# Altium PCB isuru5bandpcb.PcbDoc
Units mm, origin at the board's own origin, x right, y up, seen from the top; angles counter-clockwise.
Board outline 152.4 x 101.6 mm, 4 copper layers (Top Layer, Layer 1, Layer 2, Bottom Layer), stack 2.6 mm thick; 87 components, 68 nets, 261 pads, 4 vias.
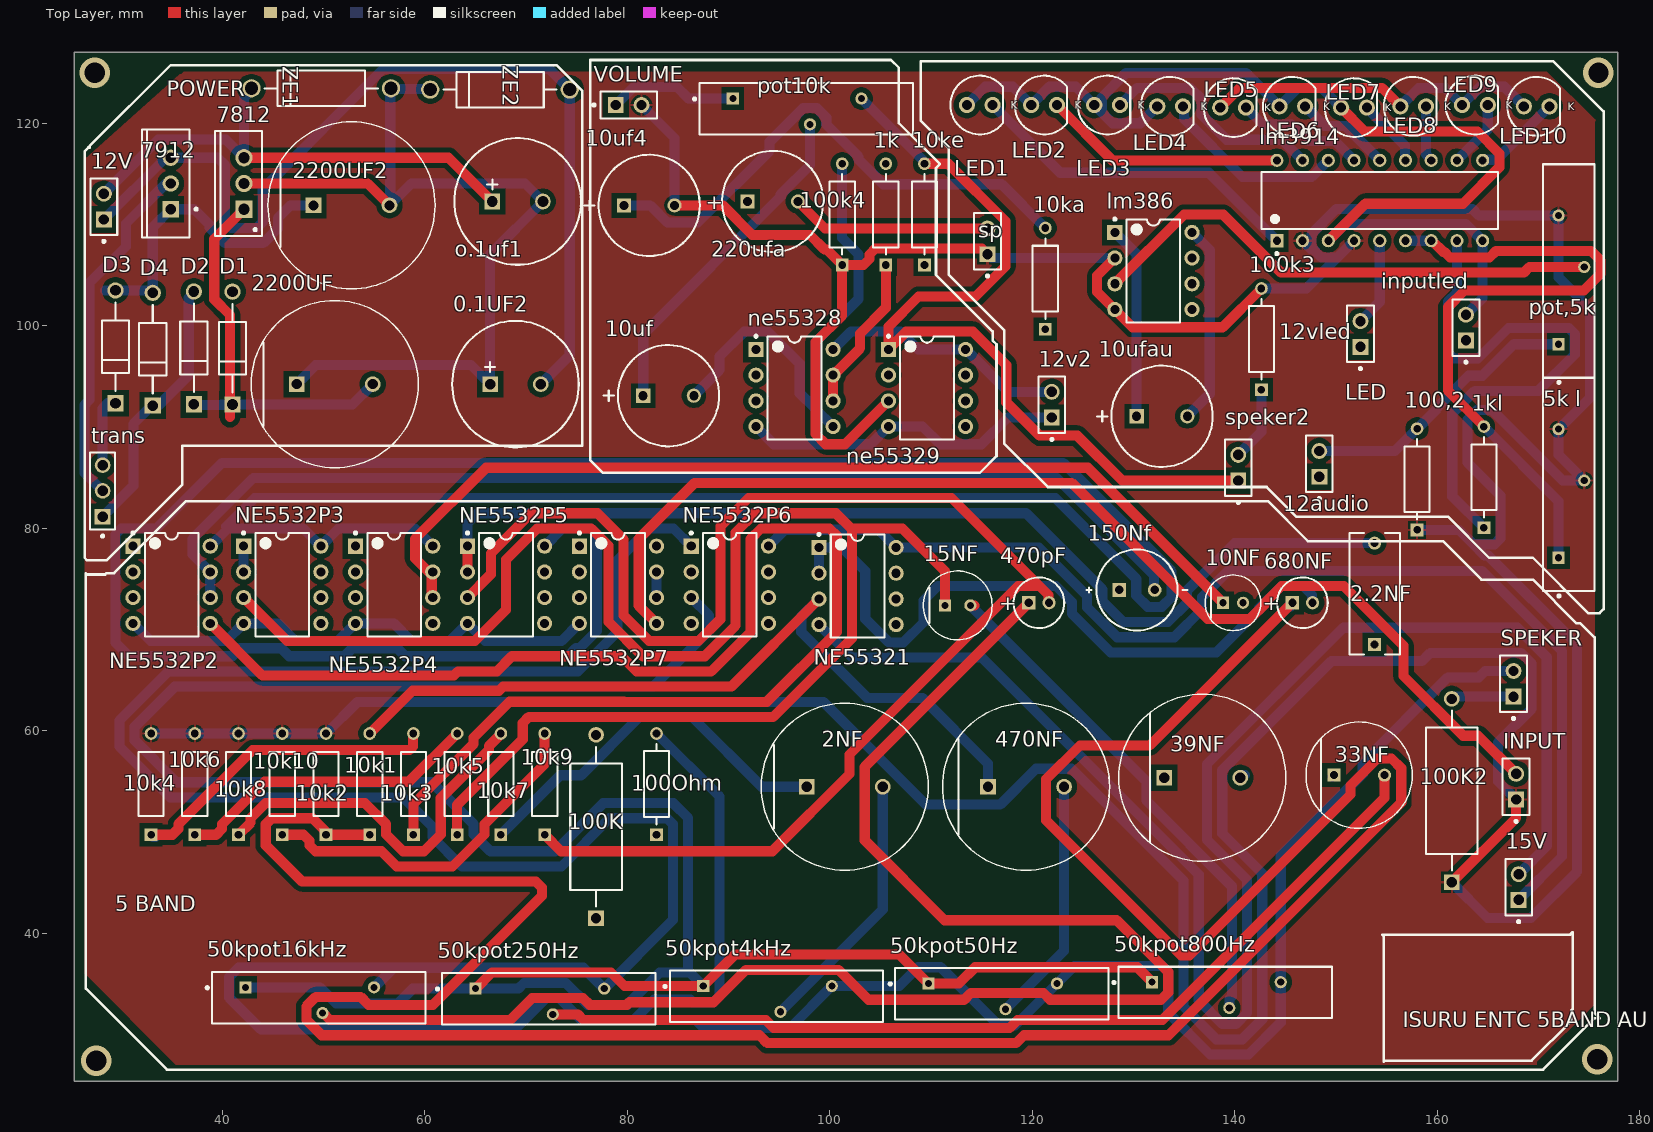
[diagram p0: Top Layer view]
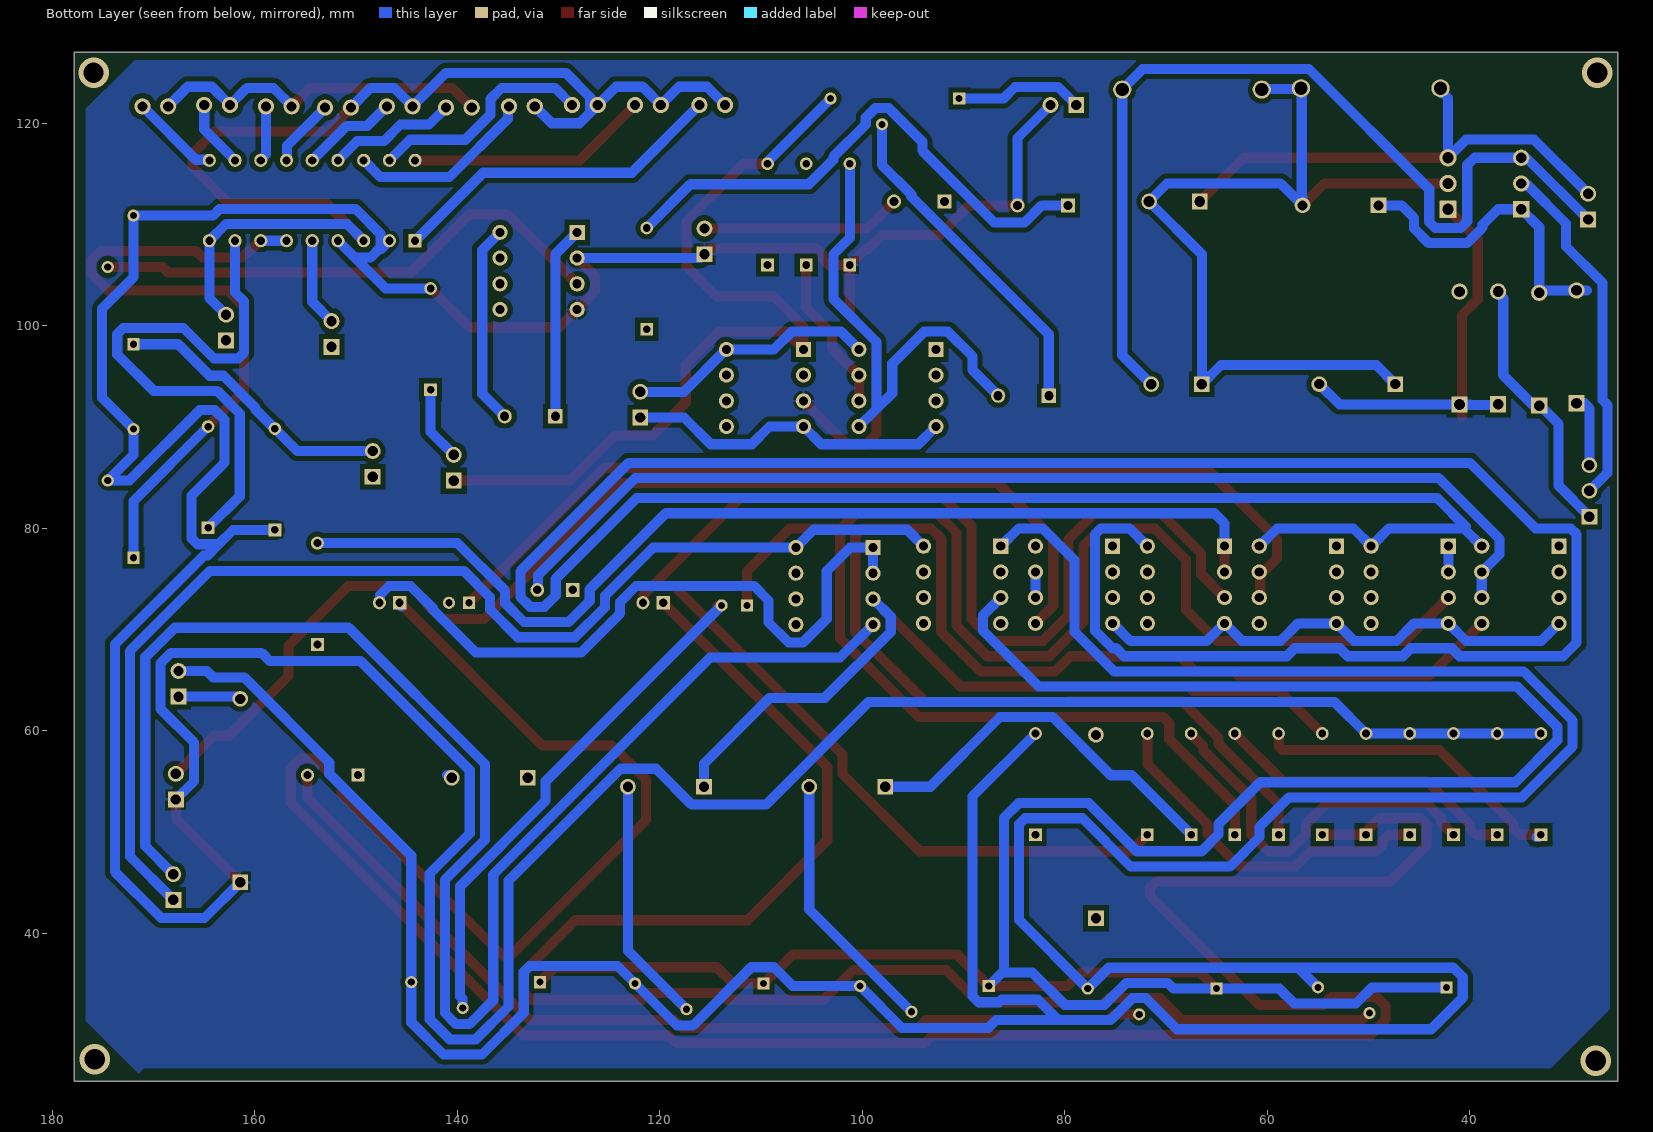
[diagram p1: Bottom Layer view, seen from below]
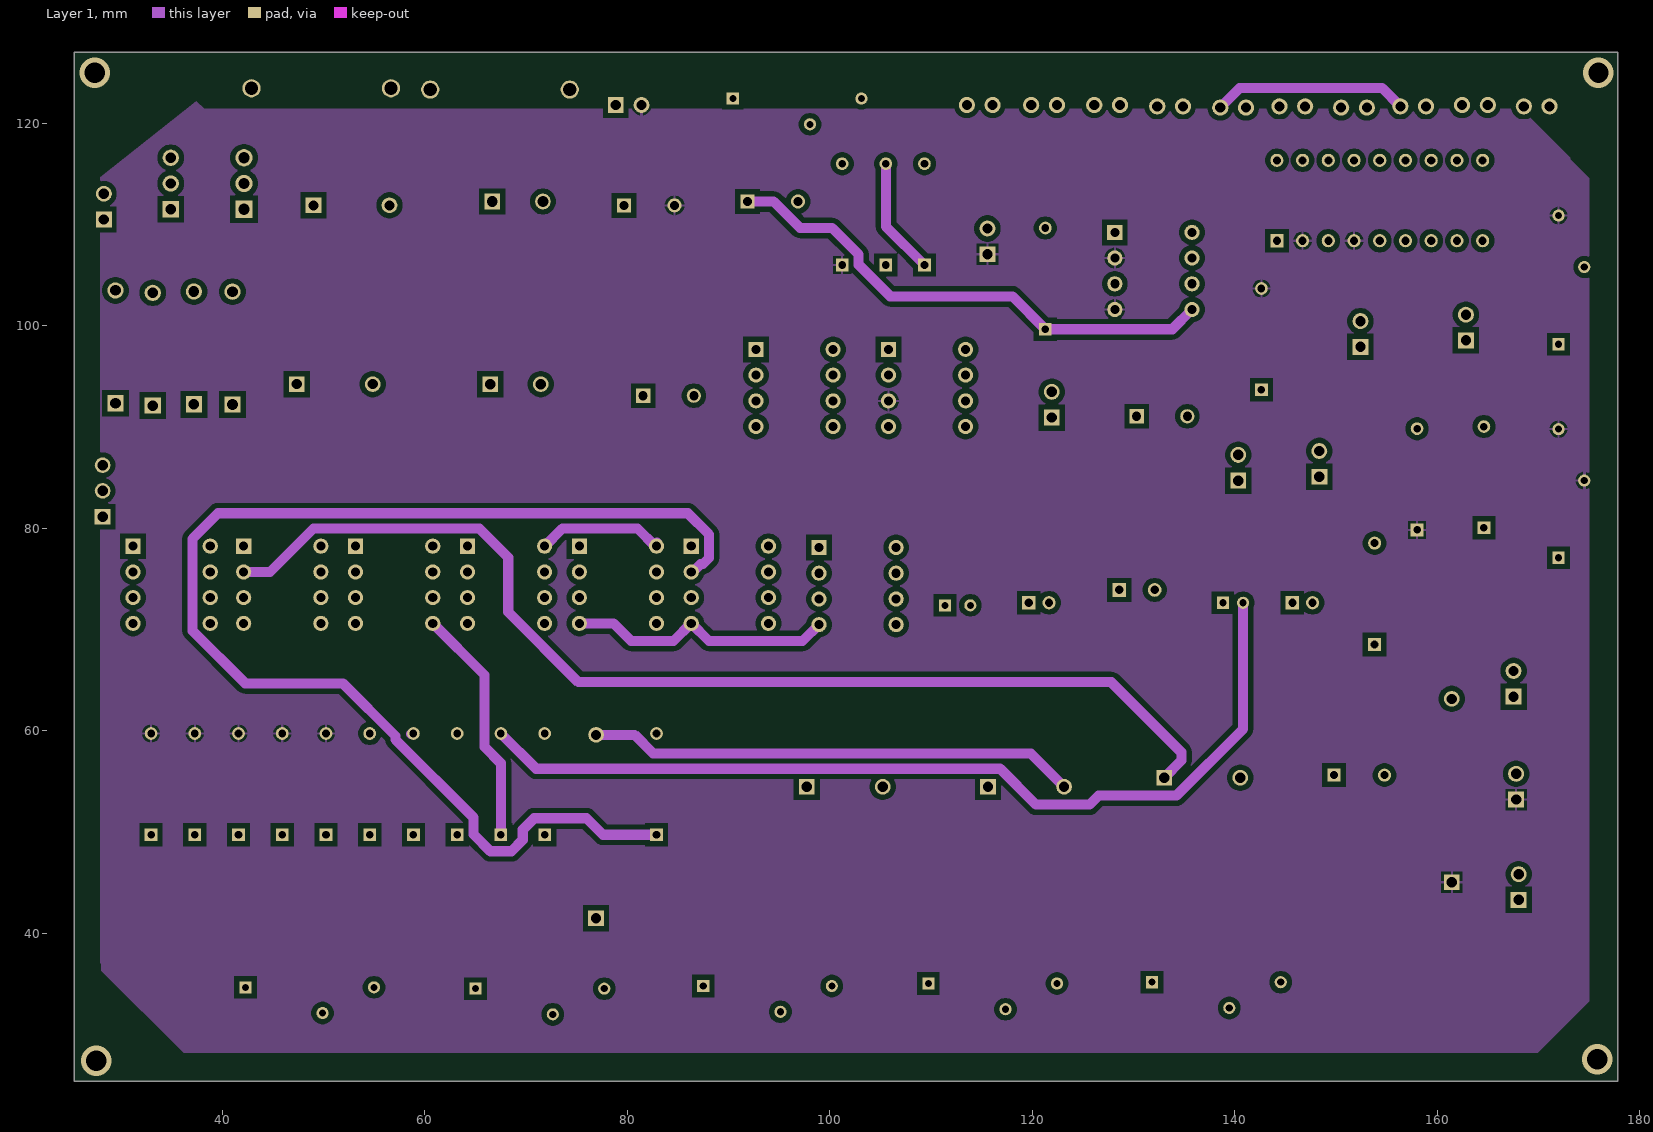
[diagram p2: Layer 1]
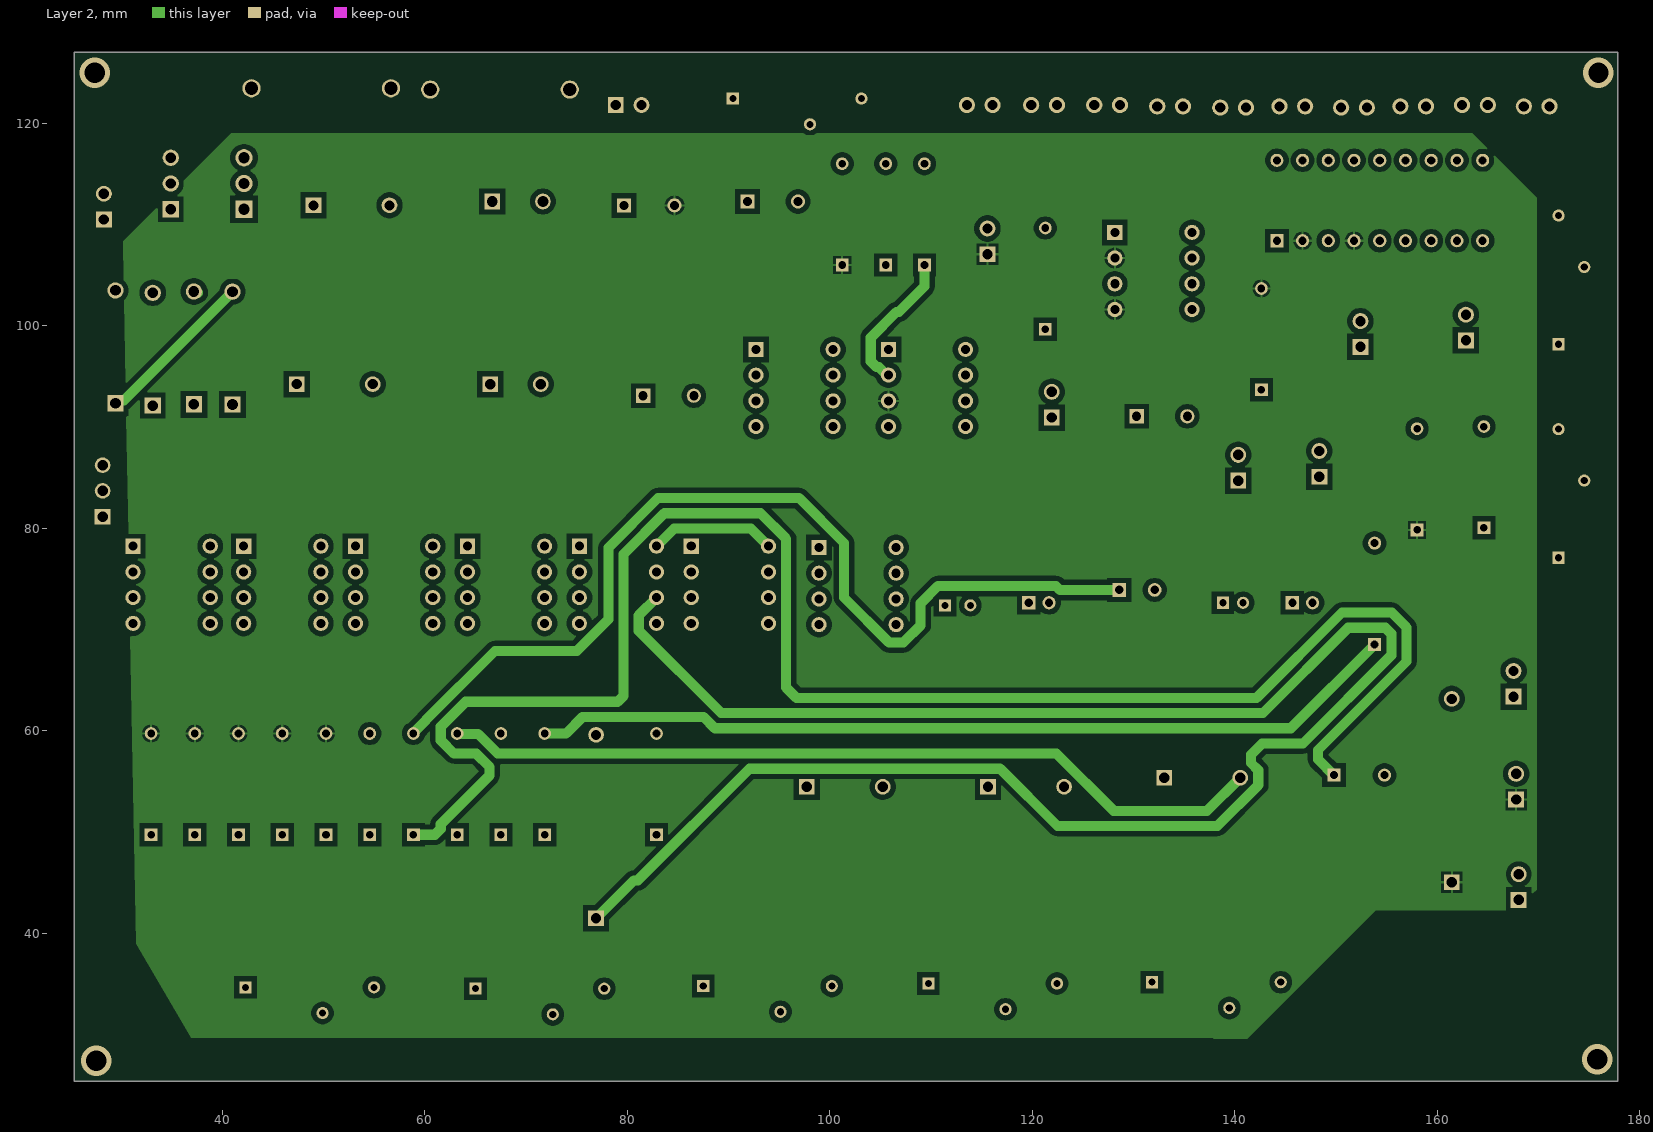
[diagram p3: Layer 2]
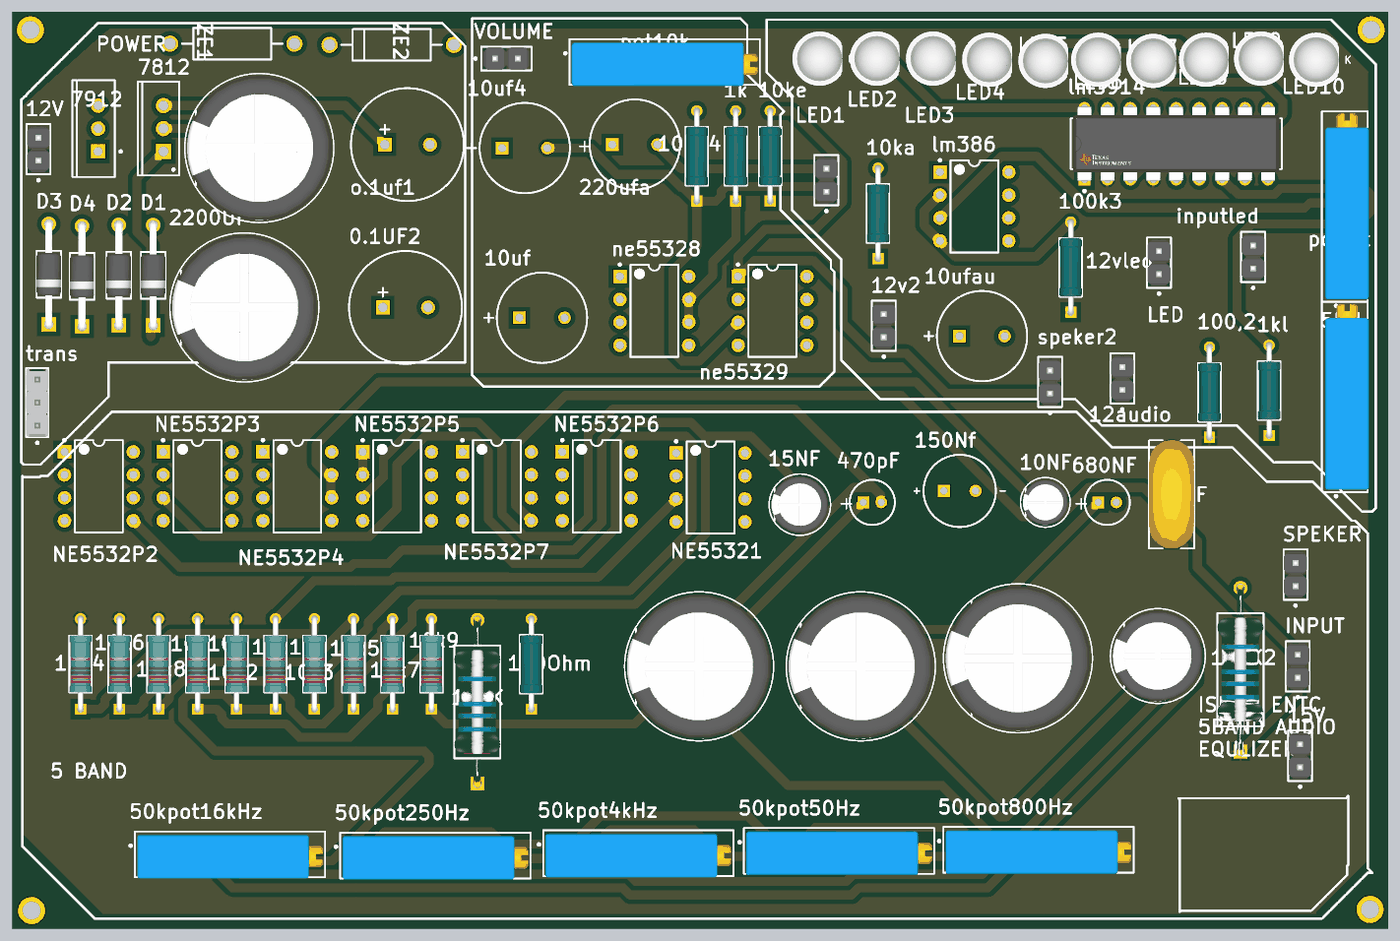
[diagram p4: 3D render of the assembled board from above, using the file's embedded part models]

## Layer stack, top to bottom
Top Solder: solder mask 0.05, Solder Resist, Dk 3.5
Top Layer: signal copper 0.1
Dielectric 2: prepreg 0.2, PP-006, Dk 4.1
Layer 1: signal copper 0.6
Dielectric 1: dielectric 0.8, FR-4, Dk 4.8
Layer 2: signal copper 0.6
Dielectric 3: prepreg 0.2, PP-006, Dk 4.1
Bottom Layer: signal copper 0.1
Bottom Solder: solder mask 0.05, Solder Resist, Dk 3.5

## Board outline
25.4,25.4 177.8,25.4 177.8,127 25.4,127

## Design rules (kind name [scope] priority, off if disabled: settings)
Clearance [All] p1: gap=0.5 ignorepadtopadclearanceinfootprint=FALSE
Height [All] p1: minheight=0 maxheight=150 prefheight=33.5
PolygonConnect [All] p1: connectstyle=Relief reliefconductorwidth=0.254 reliefentries=4 polygonreliefangle="90 Angle" airgapwidth=0.254
RoutingVias [All] p1: holewidth=2 width=3 viastyle="Through Hole" minholewidth=0.1 minwidth=1.27 maxholewidth=2 maxwidth=3
SilkToSilkClearance [All] p1: silktosilkclearance=0
SilkToSolderMaskClearance [IsPad] p1: minsilkscreentomaskgap=0 clearancetoexposedcopper=TRUE
SolderMaskExpansion [All] p1: expansion=0.102 istentingtop=FALSE
Width [All] p1: maxlimit=1 minlimit=0.254 preferedwidth=1
27 further rules are at their usual default settings.

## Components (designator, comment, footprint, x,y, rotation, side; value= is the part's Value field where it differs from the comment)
0.1UF2 "UHE1H681MHD" NIC-UHE-12.5x31.5-2_V 68.961,94.234 r0 top (schematic designator 0.1uf2)
1k "MRS25000C5620FRP00" FP-MRS25-MFG 105.537,110.998 r90 top
1kl "MRS25000C5620FRP00" FP-MRS25-MFG 164.592,85.043 r90 top
2.2NF "VY1222M47Y5UQ6TV0" FP-VY1470-MFG 153.797,73.533 r90 top
2NF "EEUHD1H561S" FP-RAD-TH-D_16_0_5-L_15_1-MFG 101.473,54.483 r0 top
"5k l" "3006P-1-103LF" FP-3006P-MFG 172.973,84.324 r90 top
10k1 "MBB02070C1002FCT00" FP-MBB0207-MFG 54.57,54.737 r90 top
10k2 "MBB02070C1002FCT00" FP-MBB0207-MFG 50.252,54.737 r90 top
10k3 "MBB02070C1002FCT00" FP-MBB0207-MFG 58.888,54.737 r90 top
10k4 "MBB02070C1002FCT00" FP-MBB0207-MFG 32.98,54.737 r90 top
10k5 "MBB02070C1002FCT00" FP-MBB0207-MFG 63.206,54.737 r90 top
10k6 "MBB02070C1002FCT00" FP-MBB0207-MFG 37.298,54.737 r90 top
10k7 "MBB02070C1002FCT00" FP-MBB0207-MFG 67.524,54.737 r90 top
10k8 "MBB02070C1002FCT00" FP-MBB0207-MFG 41.616,54.737 r90 top
10k9 "MBB02070C1002FCT00" FP-MBB0207-MFG 71.842,54.737 r90 top
10k10 "MBB02070C1002FCT00" FP-MBB0207-MFG 45.934,54.737 r90 top
10ka "MRS25000C1001FCT00" FP-MRS25-MFG 121.285,104.648 r90 top
10ke "MRS25000C1001FCT00" FP-MRS25-MFG 109.347,110.998 r90 top
10NF "EEUEB1JR47S" FP-RAD-TH-D_5_0_5-L_11_1-MFG 139.811,72.644 r0 top
10uf "EEU-EE2G100" PNSC-EEU-EE2G100-2_V 84.074,93.091 r0 top
10uf4 "EEU-EE2G100" PNSC-EEU-EE2G100-2_V 82.169,111.887 r0 top
10ufau "EEU-EE2G100" PNSC-EEU-EE2G100-2_V 132.802,91.059 r0 top
12audio "M20-9990246" FP-M20-9990246-MFG 148.336,86.36 r90 top
12V "M20-9990246" FP-M20-9990246-MFG 28.321,111.76 r90 top
12v2 "M20-9990246" FP-M20-9990246-MFG 121.92,92.202 r90 top
12vled "M20-9990246" FP-M20-9990246-MFG 152.4,99.187 r90 top
15NF "EEUFR1H470" FP-RAD-TH-D_6_3_0_5-L_11-MFG 112.629,72.39 r0 top
15V "M20-9990246" FP-M20-9990246-MFG 168.021,44.577 r90 top
33NF "EEUFR1J271UB" FP-RAD-TH-D_10_0_5-L_20_2-MFG 152.273,55.626 r0 top
39NF "ECA1HHG222" FP-RAD-TH-D_16_0_5-L_31_5-MFG 136.779,55.372 r0 top
50kpot4kHz "3006P-1-103LF" FP-3006P-MFG 94.738,33.783 r0 top
50kpot16kHz "3006P-1-103LF" FP-3006P-MFG 49.53,33.655 r0 top
50kpot50Hz "3006P-1-103LF" FP-3006P-MFG 116.967,34.036 r0 top
50kpot250Hz "3006P-1-103LF" FP-3006P-MFG 72.263,33.528 r0 top
50kpot800Hz "3006P-1-103LF" FP-3006P-MFG 139.061,34.164 r0 top
100,2 "MRS25000C1001FCT00" FP-MRS25-MFG 157.988,84.836 r90 top
100K "KNP100JR-73-22R" FP-KNP100-MFG 76.922,50.546 r90 top value=22Ω
100K2 "KNP100JR-73-22R" FP-KNP100-MFG 161.417,54.102 r90 top value=22Ω
100k3 "MRS25000C1001FCT00" FP-MRS25-MFG 142.621,98.679 r90 top
100k4 "MRS25000C1001FCT00" FP-MRS25-MFG 101.219,110.998 r90 top
100Ohm "MRS25000C1001FCT00" FP-MRS25-MFG 82.891,54.737 r90 top
150Nf "UHE1H101MPD" NIC-UHE1H101MPD 130.33,73.914 r0 top
220ufa "ECA-1HM221" CAPPR65-500-1250X1000X1350 94.361,112.268 r0 top
470NF "EEUFC2A471" FP-RAD-TH-D_16_0_5-L_40_2-MFG 119.38,54.483 r0 top
470pF "ECA1HM4R7" CAPPR55-200-1100X500X1200 120.65,72.644 r0 top
680NF "ECA-1HHG010" CAPPR55-200-1100X500X1200 146.669,72.644 r0 top
2200UF "ECA1VM222" FP-RAD-TH-D_16_0_5-L_25_2-MFG 51.114,94.234 r0 top
2200UF2 "ECA1VM222" FP-RAD-TH-D_16_0_5-L_25_2-MFG 52.772,111.887 r0 top
7812 "L7812ACV" TO220 42.164,114.046 r90 top
7912 "LM7912CT" NDE0003A 34.925,114.046 r90 top
D1 "1N4001-TP" FP-DO-41-MFG 41.021,97.79 r90 top value=15pF
D2 "1N4001-TP" FP-DO-41-MFG 37.211,97.808 r90 top value=15pF
D3 "1N4001-TP" FP-DO-41-MFG 29.464,97.917 r90 top value=15pF
D4 "1N4001-TP" FP-DO-41-MFG 33.147,97.681 r90 top value=15pF
INPUT "M20-9990246" FP-M20-9990246-MFG 167.767,54.483 r90 top
inputled "M20-9990246" FP-M20-9990246-MFG 162.814,99.822 r90 top
LED1 "151051BS04000" "Type 5mm" 114.808,121.793 r0 top
LED2 "151051BS04000" "Type 5mm" 121.158,121.793 r0 top
LED3 "151051BS04000" "Type 5mm" 127.381,121.793 r0 top
LED4 "151051BS04000" "Type 5mm" 133.604,121.666 r0 top
LED5 "151051BS04000" "Type 5mm" 139.827,121.539 r0 top
LED6 "151051BS04000" "Type 5mm" 145.669,121.666 r0 top
LED7 "151051BS04000" "Type 5mm" 151.765,121.539 r0 top
LED8 "151051BS04000" "Type 5mm" 157.607,121.666 r0 top
LED9 "151051BS04000" "Type 5mm" 163.703,121.793 r0 top
LED10 "151051BS04000" "Type 5mm" 169.799,121.666 r0 top
lm386 "LM386N-1/NOPB" P0008A 131.953,105.41 r0 top
lm3914 "LM3914N-1" FP-NFK0018A-MFG 154.305,112.363 r90 top
NE5532P2 "NE5532P" P0008A 35.012,74.422 r0 top
NE5532P3 "NE5532P" P0008A 45.934,74.422 r0 top
NE5532P4 "NE5532P" P0008A 56.983,74.422 r0 top
NE5532P5 "NE5532P" P0008A 68.032,74.422 r0 top
NE5532P6 "NE5532P" P0008A 90.13,74.422 r0 top
NE5532P7 "NE5532P" P0008A 79.081,74.422 r0 top
NE55321 "NE5532P" P0008A 102.743,74.295 r0 top
ne55328 "NE5532P" P0008A 96.52,93.853 r0 top
ne55329 "NE5532P" P0008A 109.601,93.853 r0 top
o.1uf1 "UHE1H681MHD" NIC-UHE-12.5x31.5-2_V 69.175,112.268 r0 top
pot10k "3006P-1-103LF" FP-3006P-MFG 97.659,121.413 r0 top
pot,5k "3006P-1-103LF" FP-3006P-MFG 172.974,105.41 r90 top
sp "M20-9990246" FP-M20-9990246-MFG 115.57,108.331 r90 top
SPEKER "M20-9990246" FP-M20-9990246-MFG 167.513,64.643 r90 top
speker2 "M20-9990246" FP-M20-9990246-MFG 140.335,85.979 r90 top
trans "22-28-4033" MOLX-22-28-4033_V 28.194,83.693 r90 top
VOLUME "M20-9990246" FP-M20-9990246-MFG 80.137,121.793 r0 top
ZE1 "1N5349BRLG" ONSC-SURMETIC40-2-017AA-01 49.784,123.444 r0 top
ZE2 "1N5349BRLG" ONSC-SURMETIC40-2-017AA-01 67.437,123.317 r0 top

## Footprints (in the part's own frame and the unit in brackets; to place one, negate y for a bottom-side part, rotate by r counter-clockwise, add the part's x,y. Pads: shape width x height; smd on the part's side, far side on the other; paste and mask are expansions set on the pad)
CAPPR55-200-1100X500X1200 [mm] "THD, 2-Leads, Dia 5mm, Body Length 11mm"
  rect 1.3x1.3 hole 0.8: 1(-1,0)
  round 1.3 hole 0.8: 2(1,0)
  silkscreen extent -2.5,-2.5 2.5,2.5, body extent -2.5,-2.5 2.5,2.5, height 12
CAPPR65-500-1250X1000X1350 [mm] "THD, 2-Leads, Dia 10mm, Body Length 12.5mm"
  rect 1.4x1.4 hole 0.9: 1(-2.5,0)
  round 1.4 hole 0.9: 2(2.5,0)
  silkscreen extent -5,-5 5,5, body extent -5,-5 5,5, height 13.5
FP-3006P-MFG [mm]
  rect 1.2x1.2 hole 0.7 paste-1000 mask+0: 1(-7.235,1.015)
  round 1.2 hole 0.7 paste-1000 mask+0: 2(0.385,-1.525) 3(5.465,1.015)
  silkscreen extent -11.12,-2.54 10.54,2.54, body extent -10.64,-2.64 10.64,2.64, height 0.25
FP-DO-41-MFG [mm]
  rect 1.6x1.6 hole 1.05 paste-1000 mask+0: 1(-5.57,0)
  round 1.6 hole 1.05 paste-1000 mask+0: 2(5.57,0)
  silkscreen extent -4.37,-1.35 4.37,1.35, body extent -6.47,-1.45 6.47,1.45, height 0.25
FP-KNP100-MFG [mm]
  rect 1.55x1.55 hole 1 paste-1000 mask+0: 1(-9.055,0)
  round 1.55 hole 1 paste-1000 mask+0: 2(9.055,0)
  silkscreen extent -7.88,-2.55 7.88,2.55, body extent -9.93,-2.65 9.93,2.65, height 0.25
FP-M20-9990246-MFG [mm]
  rect 1.57x1.57 hole 1.02 paste-1000 mask+0: 1(-1.27,0)
  round 1.57 hole 1.02 paste-1000 mask+0: 2(1.27,0)
  silkscreen extent -3.55,-1.32 2.79,1.32, body extent -2.89,-1.42 2.89,1.42, height 0.25
FP-MBB0207-MFG [mm]
  rect 1.25x1.25 hole 0.75 paste-1000 mask+0: 1(-5,0)
  round 1.25 hole 0.75 paste-1000 mask+0: 2(5,0)
  silkscreen extent -3.15,-1.25 3.15,1.25, body extent -5.72,-1.35 5.72,1.35, height 0.25
FP-MRS25-MFG [mm]
  rect 1.25x1.25 hole 0.75 paste-1000 mask+0: 1(-5,0)
  round 1.25 hole 0.75 paste-1000 mask+0: 2(5,0)
  silkscreen extent -3.98,-1.25 3.98,1.25, body extent -5.72,-1.35 5.72,1.35, height 0.25
FP-NFK0018A-MFG [mm]
  rect 1.3x1.3 hole 0.8 paste-1000 mask+0: 1(-3.969,10.16)
  round 1.3 hole 0.8 paste-1000 mask+0: 2(-3.969,7.62) 3(-3.969,5.08) 4(-3.969,2.54) 5(-3.969,0) 6(-3.969,-2.54) 7(-3.969,-5.08) 8(-3.969,-7.62) 9(-3.969,-10.16) 10(3.969,-10.16) 11(3.969,-7.62) 12(3.969,-5.08) 13(3.969,-2.54) 14(3.969,0) 15(3.969,2.54) 16(3.969,5.08) 17(3.969,7.62) 18(3.969,10.16)
  silkscreen extent -5.37,-11.68 2.8,11.68, body extent -4.72,-12.04 4.72,12.04, height 0.25
FP-RAD-TH-D_5_0_5-L_11_1-MFG [mm]
  rect 1.2x1.2 hole 0.7 paste-1000 mask+0: 1(-1,0)
  round 1.2 hole 0.7 paste-1000 mask+0: 2(1,0)
  silkscreen extent -2.75,-2.75 2.75,2.75, body extent -2.85,-2.85 2.85,2.85, height 0.25
FP-RAD-TH-D_6_3_0_5-L_11-MFG [mm]
  rect 1.2x1.2 hole 0.7 paste-1000 mask+0: 1(-1.25,0)
  round 1.2 hole 0.7 paste-1000 mask+0: 2(1.25,0)
  silkscreen extent -3.4,-3.4 3.4,3.4, body extent -3.5,-3.5 3.5,3.5, height 0.25
FP-RAD-TH-D_10_0_5-L_20_2-MFG [mm]
  rect 1.3x1.3 hole 0.8 paste-1000 mask+0: 1(-2.5,0)
  round 1.3 hole 0.8 paste-1000 mask+0: 2(2.5,0)
  silkscreen extent -5.25,-5.25 5.25,5.25, body extent -5.35,-5.35 5.35,5.35, height 0.25
FP-RAD-TH-D_16_0_5-L_15_1-MFG [mm]
  rect 1.55x1.55 hole 1 paste-1000 mask+0: 1(-3.75,0)
  round 1.55 hole 1 paste-1000 mask+0: 2(3.75,0)
  silkscreen extent -8.25,-8.25 8.25,8.25, body extent -8.35,-8.35 8.35,8.35, height 0.25
FP-RAD-TH-D_16_0_5-L_25_2-MFG [mm]
  rect 1.55x1.55 hole 1 paste-1000 mask+0: 1(-3.75,0)
  round 1.55 hole 1 paste-1000 mask+0: 2(3.75,0)
  silkscreen extent -8.25,-8.25 8.25,8.25, body extent -8.35,-8.35 8.35,8.35, height 0.25
FP-RAD-TH-D_16_0_5-L_31_5-MFG [mm]
  rect 1.55x1.55 hole 1 paste-1000 mask+0: 1(-3.75,0)
  round 1.55 hole 1 paste-1000 mask+0: 2(3.75,0)
  silkscreen extent -8.25,-8.25 8.25,8.25, body extent -8.35,-8.35 8.35,8.35, height 0.25
FP-RAD-TH-D_16_0_5-L_40_2-MFG [mm]
  rect 1.55x1.55 hole 1 paste-1000 mask+0: 1(-3.75,0)
  round 1.55 hole 1 paste-1000 mask+0: 2(3.75,0)
  silkscreen extent -8.25,-8.25 8.25,8.25, body extent -8.35,-8.35 8.35,8.35, height 0.25
FP-VY1470-MFG [mm]
  rect 1.3x1.3 hole 0.8 paste-1000 mask+0: 1(-5,0)
  round 1.3 hole 0.8 paste-1000 mask+0: 2(5,0)
  silkscreen extent -6,-2.5 6,2.5, body extent -6.1,-2.6 6.1,2.6, height 0.25
MOLX-22-28-4033_V [mm] "THD, 3-Leads, Body 7.62x2.49mm, Pitch 2.54mm"
  rect 1.55x1.55 hole 1.02: 1(-2.54,0)
  round 1.55 hole 1.02: 2(0,0) 3(2.54,0)
  silkscreen extent -4.58,-1.24 3.81,1.24, body extent -3.81,-1.24 3.81,1.24, height 8.38
NDE0003A [mm] "FM, 3-Leads, Body 10.7x4.7mm, Pitch 2.54mm"
  rect 1.6x1.6 hole 1: 1(-2.54,0)
  round 1.6 hole 1: 2(0,0) 3(2.54,0)
  silkscreen extent -5.35,-2.63 5.35,2.85, body extent -5.4,-1.9 5.4,2.9, height 19.4
NIC-UHE1H101MPD [mm] "THD, 2-Leads, Dia 8mm"
  rect 1.35x1.35 hole 0.85: 1(-1.75,0)
  round 1.35 hole 0.85: 2(1.75,0)
  silkscreen extent -5,-4 5,4, body extent -4,-4 4,4, height 13
NIC-UHE-12.5x31.5-2_V [mm] "THD, 2-Leads, Dia 12.5mm, Body Length 31.5mm, Pin Spacing 5mm"
  rect 1.55x1.55 hole 1.05: 1(-2.5,0)
  round 1.55 hole 1.05: 2(2.5,0)
  silkscreen extent -6.25,-6.25 6.25,6.25, body extent -6.25,-6.25 6.25,6.25, height 33.5
ONSC-SURMETIC40-2-017AA-01 [mm] "AXIAL, 2-Leads, Diameter 3.49mm"
  round 1.8 hole 1.3: 1(-6.887,0) 2(6.887,0)
  silkscreen extent -5.59,-1.75 5.59,1.75
P0008A [mm] "DIP, 8-Leads, Body 10.15x6.6mm, Pitch 2.54mm"
  rect 1.5x1.5 hole 0.9: 1(-3.81,3.81)
  round 1.5 hole 0.9: 2(-3.81,1.27) 3(-3.81,-1.27) 4(-3.81,-3.81) 5(3.81,-3.81) 6(3.81,-1.27) 7(3.81,1.27) 8(3.81,3.81)
  silkscreen extent -3.93,-5.1 2.65,5.23, body extent -3.95,-5.07 3.95,5.07, height 5.08
PNSC-EEU-EE2G100-2_V [mm] "Through-hole, 2-Leads, Base 10x10mm, Height 22mm"
  rect 1.4x1.4 hole 0.9: 1(-2.5,0)
  round 1.4 hole 0.9: 2(2.5,0)
  silkscreen extent -6.4,-5 5,5, body extent -5,-5 5,5, height 22
TO220 [mm] "TO, Thru-Hole, Vertical, Heatsink Mounted; 3 In-Line Leads; Pitch 2.54 mm"
  rect 1.7x1.7 hole 1.1: 1(-2.54,0)
  round 1.7 hole 1.1: 2(0,0) 3(2.54,0)
  silkscreen extent -5.2,-1.75 5.2,2.85, body extent -5.25,-1.8 5.25,2.9, height 19.7
"Type 5mm" [mm] "THT, LED-5mm, 2pin- Body 5.8mm"
  round 1.6 hole 1: 1(1.27,0) 2(-1.27,0)
  silkscreen extent -2.9,-2.9 2.29,2.9, body extent -2.9,-2.9 2.5,2.9, height 11.7

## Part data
0.1UF2 o.1uf1: library part CMP-1253-00001-1, "Aluminum Electrolytic Capacitor, 680 uF +/-20%, 50 V, -40 to 105 degC, 2-Pin THD, RoHS, Bulk", Capacitance Tolerance=+/-20%, Manufacturer=Nichicon, Rated Capacitance="680 uF", Rated Voltage="50 V", Temperature Range="-40 to 105 degC"
1k 1kl: library part CMP-02408-000052-1, "RES 562 OHM 0.6W 1% AXIAL", Case/Package=Axial, Max Operating Temperature=155°C, Max Power Dissipation=600mW, Min Operating Temperature=-55°C, Package Quantity=1, Resistance=562R, Resistor Type="Thin Film", Temperature Coefficient=50ppm/°C, Tolerance=1%, Voltage Rating=350V
2.2NF: library part CMP-02417-000069-1, "CAP CER 2200PF 760VAC Y5U RADIAL", Capacitance=2.2nF, Case/Package=Radial, Dielectric=Y5U, Max Operating Temperature=125°C, Min Operating Temperature=-40°C, Package Quantity=500, Ratings=X1, Resistor Type=Ceramic, Tolerance=20%, Voltage=500V
2NF: library part CMP-05427-001618-1, "Aluminum Electrolytic Capacitors (Radial Lead Type) AEC-Q200 Qualified 560uF ±20% 50V", Capacitance=560uF, Case/Package=Radial, Max Operating Temperature=105°C, Min Operating Temperature=-55°C, Package Quantity=100, Ripple Current=650mA, Tolerance=20%, Voltage=50V
"5k l" 50kpot4kHz 50kpot16kHz 50kpot50Hz 50kpot250Hz 50kpot800Hz pot10k pot,5k: library part CMP-07234-000047-1, "TRIMMER 10KOHM 0.75W PC PIN SIDE", Color=Blue, Insulation Resistance=1GR, Manufacturer Series=3006, Max Operating Temperature=125°C, Max Power Dissipation=750mW, Min Operating Temperature=-55°C, Package Quantity=100, Resistance=10kR, Resistance Law=Linear, Resistance Tolerance=10%, Resistor Type=Cermet, Temperature Coefficient=100ppm/°C
10k1 10k2 10k3 10k4 10k5 10k6 10k7 10k8 10k9 10k10: library part CMP-02408-000035-1, "RES 10K OHM 0.6W 1% AXIAL", Case/Package=Conformal, Max Operating Temperature=155°C, Max Power Dissipation=600mW, Min Operating Temperature=-55°C, Resistance=10kR, Resistance Tolerance=1%, Resistor Type="Metal Film", Temperature Coefficient=50ppm/°C, Voltage Rating=300V
10ka 10ke 100,2 100k3 100k4 100Ohm: library part CMP-02408-000051-1, "RES 1K OHM 0.6W 1% AXIAL", Case/Package=Axial, Max Operating Temperature=155°C, Max Power Dissipation=600mW, Min Operating Temperature=-55°C, Package Quantity=5000, Resistance=1kR, Resistance Tolerance=1%, Resistor Type="Metal Film", Temperature Coefficient=50ppm/°C, Voltage Rating=350V
10NF: library part CMP-05427-001047-1, "Aluminum Electrolytic Capacitors (Radial Lead Type) 0.47uF ±20% 63V", Capacitance=470nF, Case/Package=Radial, Leakage Current=3uA, Max Operating Temperature=105°C, Min Operating Temperature=-40°C, Package Quantity=200, Ripple Current=4.5mA, Tolerance=20%, Voltage=63V
10uf 10uf4 10ufau: library part CMP-0736-00002-1, "Aluminum Electrolytic Capacitor, 10 uF +/- 20%, 400 V, -25 to 105 degC, 2-Pin 10 x 10 x 22 mm Through-hole, RoHS, Tape and Reel", Capacitance Tolerance="+/- 20%", Manufacturer=Panasonic, Rated Voltage="400 V", Ripple Current="430 mA", Temp. Range="-25 to 105 degC"
12audio 12V 12v2 12vled 15V INPUT inputled sp SPEKER speker2 VOLUME: library part CMP-15831-000009-1, "CONN HEADER VERT 2POS 2.54MM", Current Rating=3A, Manufacturer=Harwin, Temperature="-40°C to +105°C", Temperature Range High=+105°C, Temperature Range Low=-40°C
15NF: library part CMP-05427-001321-1, "Aluminum Electrolytic Capacitors (Radial Lead Type) 47uF ±20% 50V", Capacitance=47uF, Case/Package=Radial, Max Operating Temperature=105°C, Min Operating Temperature=-40°C, Ripple Current=405mA, Tolerance=20%, Voltage=50V
33NF: library part CMP-05427-000491-1, "Aluminum Electrolytic Capacitors (Radial Lead Type) 270uF ±20% 63V", Capacitance=270uF, Case/Package=Radial, ESR (Equivalent Series Resistance)=35mR, Max Operating Temperature=105°C, Min Operating Temperature=-40°C, Package Quantity=1, Ripple Current=1.229A, Tolerance=20%, Voltage Rating=63V
39NF: library part CMP-05427-001651-1, "Aluminum Electrolytic Capacitors (Radial Lead Type) AEC-Q200 Qualified 2200uF ±20% 50V", Capacitance=2.2mF, Case/Package=Radial, Leakage Current=3uA, Max Operating Temperature=105°C, Min Operating Temperature=-55°C, Package Quantity=100, Ripple Current=1.47A, Tolerance=20%, Voltage=50V
100K 100K2: library part CMP-03413-000004-1, "RES 22 OHM 1W 5% AXIAL", Manufacturer=Yageo, Package=KNP100, Power Rating=1W, Resistance=22Ω, Temperature="-40°C to +200°C", Temperature Coefficient=300ppm/°C, Temperature Range High=+200°C, Temperature Range Low=-40°C, Tolerance=5%
150Nf: library part CMP-2000-07349-1, "Aluminium Electrolytic Capacitor, 100 uF, +/- 20%, 50 V, -40 to 105 degC, 2-Pin THD, RoHS, Bulk", Capacitance=100µF, Case Size/Dimension=Ø8x11.5mm, Manufacturer=Nichicon, Operating Temp-Max=105°C, Package Description="2-Pin Through Hole Device, Dia 8 mm, Body Length 11.5 mm", Rated Voltage=50V
220ufa: library part CMP-1665-00043-1, "Aluminum Electrolytic Capacitor, 220 uF, +/- 20%, 50 V, -40 to 85 degC, 2-Pin THD, RoHS, Bulk", Case\Package=SOIC, Max Operating Temperature="70 degC", Max Supply Voltage="5.5 V", Min Operating Temperature="0 degC", Min Supply Voltage="4.5 V", Nominal Supply Current="10 mA", Nominal Supply Voltage="5 V", Package Quantity=50
470NF: library part CMP-05427-000270-1, "Aluminum Electrolytic Capacitors (Radial Lead Type) AEC-Q200 Qualified 470uF ±20% 100V", Capacitance=470uF, Case/Package=Radial, Dielectric Material=Aluminium, ESR (Equivalent Series Resistance)=47mR, Leakage Current=3uA, Max Operating Temperature=105°C, Min Operating Temperature=-55°C, Package Quantity=100, Ratings=AEC-Q200, Ripple Current=1.92A, Tolerance=20%, Voltage=100V
470pF: library part CMP-1665-00037-2, "Aluminum Electrolytic Capacitor, 4.7 uF, +/- 20%, 50 V, -40 to 85 degC, 2-Pin THD, RoHS, Bulk", Capacitance=4.7uF, Case/Package=Radial, Dielectric Material=Aluminium, Leakage Current=3uA, Manufacturer=Panasonic, Max Operating Temperature=85degC, Min Operating Temperature=-40degC, Package Description="2-Pin Radial Lead, Dia 5 mm, Height 12 mm", Package Quantity=200, Package Reference=CAPPR55-200-1100X500X1200, Ripple Current=45mA, Tolerance=20%, Voltage=50V
680NF: library part CMP-1665-00039-1, "Aluminum Electrolytic Capacitor, 1 uF, +/- 20%, 50 V, -55 to 105 degC, 2-Pin THD, RoHS, Bulk", Max Operating Temperature="70 degC", Min Operating Temperature="-30 degC", Package Quantity=150
2200UF 2200UF2: library part CMP-05427-001795-1, "Aluminum Electrolytic Capacitors (Radial Lead Type) 2200uF ±20% 35V", Capacitance=2.2mF, Case/Package=Radial, Leakage Current=3uA, Max Operating Temperature=85°C, Min Operating Temperature=-40°C, Package Quantity=100, Ripple Current=1.25A, Tolerance=20%, Voltage=35V
7812: library part CMP-0244-00451-1, "Positive Voltage Regulator, 12V, 3-Pin TO-220"
7912: library part CMP-0062-02472-3, "3-Terminal Negative Regulator, 3-pin TO-220", Manufacturer="Texas Instruments", PackageTopMarking=NSUZXYTTE#*LM7912CT, PowerWise=N
D1 D2 D3 D4: library part CMP-56207-000001-1, "DIODE GEN PURP 50V 1A DO41", Capacitance=15pF, Forward Current=1A, Manufacturer="Micro Commercial", Max Junction Temp=+150°C, Max Repetitive Reverse Voltage=50V, Max Surge Forward Current=30A, Package=DO-41, Peak Reverse Current=5uA, Temperature="-55°C to +150°C", Temperature Range Low=-55°C
LED1 LED2 LED3 LED4 LED5 LED6 LED7 LED8 LED9 LED10: library part CMP-1488-00009-1, "THT LED round mono-color color lens, WL-TMRW, Blue", Emitting color=Blue, Manufacturer="Wuerth Elektronik"
lm386: library part CMP-0057-00052-4, "Low Voltage Audio Power Amplifier, 8-pin MDIP, Pb-Free", Manufacturer="Texas Instruments", PackageTopMarking=NSUZXYTTE#*LM*386N-1, PowerWise=N
lm3914: library part CMP-0058-00006-4, "IC DRVR DOT/BAR DISPLAY 18DIP", Case/Package=DIP, Max Input Voltage=12V, Max Operating Temperature=70°C, Max Output Voltage=1.34V, Max Power Dissipation=1.365W, Max Supply Current=9.2kA, Max Supply Voltage=25V, Min Input Voltage=1.2V, Min Operating Temperature=0°C, Nominal Supply Current=9.2mA, Operating Supply Current=6.1mA, Output Current=30mA, Output Voltage=1.28V, Package Quantity=20
NE5532P2 NE5532P3 NE5532P4 NE5532P5 NE5532P6 NE5532P7 NE55321 ne55328 ne55329: library part CMP-0017-00910-2, "Dual Low-Noise High-Speed Audio Operational Amplifier, 10 to 30 V, 0 to 70 degC, 8-pin DIP (P8), Pb-Free (RoHS)", Manufacturer="Texas Instruments", Total Supply Voltage(Max)(+5V is 5, +/-5V is 10)=30, Total Supply Voltage(Min)(+5V is 5, +/-5V is 10)=10
trans: library part CMP-1676-00001-5, "Male Header, Pitch 2.54 mm, 1 x 3 Position, Height 8.38 mm, Tail Length 3.18 mm, RoHS, Bulk", Colour=Black, Current Rating="4 A", Manufacturer=Molex, Max Operating Temperature="75 degC", Min Operating Temperature="0 degC", Package Quantity=1, Voltage Rating="250 V"
ZE1 ZE2: library part CMP-1060-01279-1, "5 W Zener Voltage Regulator, 2-Pin Surmetic(TM) 40, Pb-Free, Tape and Reel", Manufacturer="On Semiconductor"

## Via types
v1: diameter 3, hole 2, Top Layer to Bottom Layer, 4 vias

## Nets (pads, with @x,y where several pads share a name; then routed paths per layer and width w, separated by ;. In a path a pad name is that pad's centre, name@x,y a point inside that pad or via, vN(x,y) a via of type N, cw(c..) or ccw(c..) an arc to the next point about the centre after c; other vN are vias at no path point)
GND: 10k2.2 10k4.2 10k6.2 10k8.2 10k10.2 10uf4.2 100,2.1 100K2.1 100k3.2 100k4.1 "5k l.2" "5k l.3" INPUT.1 lm386.2 lm386.4 lm3914.2 lm3914.4 ne55329.3 pot,5k.3 sp.1 VOLUME.2 | length 494.6
  Top Layer w1: 10uf4.2 89.428,111.887 92.348,108.967 98.041,108.967 99.463,107.545 99.672,107.545 100k4.1 ; ne55329.3 101.501,88.293 99.605,88.293 98.58,89.318 98.58,98.388 101.219,101.027 100k4.1 ; sp.1 115.008,107.623 104.498,107.623 103.912,107.037 103.912,106.584 103.326,105.998 100k4.1 ; lm386.2 126.393,104.93 126.393,103.35 lm386.4 129.893,99.85 138.792,99.85 100k3.2 ; 100K2.1 167.767,51.397 INPUT.1
  Bottom Layer w1: 10k4.2 10k6.2 10k8.2 10k10.2 10k2.2 53.377,62.862 99.354,62.862 109.508,52.708 116.819,52.708 120.369,56.258 123.865,56.258 134.926,45.197 134.926,32.775 138.162,29.539 140.73,29.539 142.7,31.509 142.7,45.909 138.754,49.855 138.754,56.107 149.53,66.883 158.484,66.883 159.299,67.698 168.252,67.698 169.298,66.652 169.298,62.174 165.982,58.858 165.982,54.998 INPUT.1 ; VOLUME.2 84.669,118.531 10uf4.2 ; sp.1 115.951,106.68 lm386.2 ; 100k3.2 147.05,103.679 150.115,106.745 ; lm3914.2 147.472,107.608 ; lm3914.4 150.115,106.745 ; 157.988,79.836 162.135,79.836 163.553,78.418 ; 100K2.1 164.942,41.522 169.22,41.522 173.798,46.1 173.798,68.516 165.02,77.294 164.677,77.294 163.553,78.418 ; 150.115,106.745 148.542,106.745 147.575,107.711 147.575,109.078 150.042,111.544 163.436,111.544 164.106,110.875 171.959,110.875 171.959,104.791 175.059,101.691 175.059,92.89 171.958,89.789 171.958,87.249 174.498,84.709 172.377,84.709 165.418,91.668 163.919,91.668 162.967,90.716 162.967,86.485 166.217,83.235 166.217,79.004 165.631,78.418 163.553,78.418
Net0.1UF2_1: 0.1UF2.1 2200UF2.2 2200UF.1 7812.2 o.1uf1.2 ZE1.2 ZE2.1 | length 88
  Top Layer w1: 7812.2 54.363,114.046 2200UF2.2
  Bottom Layer w1: 2200UF.1 49.245,96.115 64.58,96.115 0.1UF2.1 66.461,107.054 o.1uf1.2 69.9,114.043 58.678,114.043 2200UF2.2@56.9,112.264 ; 2200UF2.2@56.515,112.649 56.515,111.894 2200UF2.2 2200UF2.2@56.597,111.962 ; 2200UF2.2@56.597,112.649 56.597,123.369 ZE1.2 56.735,123.38 60.486,123.38 ZE2.1
Net0.1UF2_2: 0.1UF2.2 12V.1 7912.3 ZE2.2 | length 93.5
  Bottom Layer w1: 12V.1 7912.3@34.302,116.471 ; 7912.3 39.548,116.586 40.252,115.882 40.252,110.304 40.9,109.656 43.428,109.656 44.014,110.242 44.014,111.275 44.014,113.474 55.884,125.344 72.298,125.344 ZE2.2 74.324,97.097 0.1UF2.2
Net1k_1: 1k.1 ne55328.6 ne55328.7 | length 15.6
  Top Layer w1: ne55328.6 ne55328.7 102.999,97.792 102.999,99.242 105.537,101.78 1k.1
Net1k_2: 1k.2 10ke.1 ne55329.2 | length 25.7
  Layer 1 w1: 1k.2 105.537,109.808 10ke.1
  Layer 2 w1: ne55329.2 105.656,95.123 104.866,95.913 104.627,95.913 104.041,96.499 104.041,98.827 106.57,101.357 106.818,101.357 109.347,103.886 10ke.1
Net1kl_1: 1kl.1 lm3914.8 | length 54.8
  Bottom Layer w1: lm3914.8 161.925,103.281 161.029,102.385 161.029,97.353 161.615,96.767 164.013,96.767 167.021,99.775 172.973,99.775 173.559,99.189 173.559,97.161 169.965,93.567 163.696,93.567 161.467,91.337 161.467,83.168 1kl.1
Net1kl_2: 1kl.2 "5k l.1" lm3914.6 lm3914.7 | length 67.6
  Top Layer w1: lm3914.7 159.466,108.394 160.566,107.295 160.691,107.295 161.242,106.745 163.782,106.745 165.148,106.745 165.799,107.395 175.162,107.395 176.099,106.458 176.099,105.132 174.449,103.482 162.679,103.482 161.029,101.831 161.029,93.606 1kl.2
  Bottom Layer w1: lm3914.6 lm3914.7 ; 1kl.2 171.958,82.677 171.958,77.089
Net2.2NF_1: 2.2NF.1 10k9.2 10k10.1 | length 121.8
  Top Layer w1: 10k10.1 48.041,49.737 48.627,49.151 48.627,48.698 49.213,48.112 55.727,48.112 57.227,46.612 62.745,46.612 65.899,49.766 65.899,50.776 71.842,56.719 10k9.2
  Layer 2 w1: 10k9.2 71.845,59.74 73.967,59.74 75.603,61.376 87.531,61.376 88.653,60.254 145.518,60.254 2.2NF.1
Net2.2NF_2: 2.2NF.2 NE5532P5.1 NE5532P5.2 | length 103.8
  Top Layer w1: NE5532P5.2 NE5532P5.1
  Bottom Layer w1: NE5532P5.1 64.222,80.482 65.222,81.482 119.388,81.482 126.905,73.965 126.905,72.825 128.991,70.739 133.395,70.739 135.255,72.599 135.255,73.824 139.964,78.533 2.2NF.2
Net2NF_1: 2NF.1 10k7.1 NE5532P4.5 | length 61.5
  Layer 1 w1: NE5532P4.5 65.899,65.506 65.899,58.429 67.524,56.804 10k7.1
  Bottom Layer w1: 10k7.1 73.399,55.612 75.443,55.612 81.193,61.362 86.393,61.362 93.272,54.483 2NF.1
Net2NF_2: 2NF.2 50kpot4kHz.2 | length 26.4
  Bottom Layer w1: 50kpot4kHz.2 105.223,42.358 2NF.2
Net10k1_1: 10k1.1 10k2.1 680NF.1 | length 280.7
  Top Layer w1: 10k1.1 50.545,49.737 48.92,51.362 44.895,51.362 44.309,50.776 44.309,48.698 47.895,45.112 70.983,45.112 71.569,44.526 71.569,43.698 60.814,32.943 54.459,32.943 53.672,33.73 49.252,33.73 48.315,32.793 48.315,31.467 49.839,29.943 93.054,29.943 93.839,29.158 118.383,29.158 119.168,29.943 133.447,29.943 156.423,52.919 156.423,56.309 155.456,57.276 154.09,57.276 151.423,54.609 151.423,53.722 135.525,37.825 134.697,37.825 121.355,51.166 121.355,55.218 124.696,58.56 131.585,58.56 680NF.1
  Bottom Layer w1: 680NF.1@145.542,72.263 145.542,72.517 680NF.1
Net10k1_2: 10k1.2 470NF.1 NE55321.3 | length 80.3
  Top Layer w1: 10k1.2 58.796,63.963 67.331,63.963 67.744,64.376 80.288,64.376 80.302,64.362 90.27,64.362 NE55321.3
  Bottom Layer w1: NE55321.3 97.183,71.275 97.183,69.76 103.684,63.259 109.129,63.259 115.63,56.758 470NF.1 115.63,54.296 470NF.1@115.697,54.229
Net10k3_1: 10k3.1 33NF.1 NE5532P2.5 | length 308.7
  Top Layer w1: NE5532P2.5 43.971,65.463 62.879,65.463 63.278,65.862 67.108,65.862 68.608,67.362 79.423,67.362 80.923,65.862 88.288,65.862 92.19,69.764 92.19,78.957 93.215,79.982 99.97,79.982 100.683,79.269 100.683,69.76 93.785,62.862 79.681,62.862 79.667,62.876 68.365,62.876 64.831,59.342 64.831,58.712 58.888,52.769 10k3.1
  Layer 2 w1: 10k3.1 60.995,49.737 61.581,50.323 61.581,50.776 66.409,55.604 66.409,56.433 65.093,57.748 62.897,57.748 61.581,59.064 61.581,60.41 64.047,62.876 79.055,62.876 79.641,63.462 79.641,77.457 83.666,81.482 93.165,81.482 95.69,78.957 95.69,64.266 96.702,63.254 142.145,63.254 150.574,71.683 155.483,71.683 156.947,70.219 156.947,66.847 148.209,58.109 148.209,57.19 33NF.1
  Bottom Layer w1: 10k3.1@58.801,49.784 58.841,49.784 10k3.1 ; 33NF.1@149.646,55.499 33NF.1
Net10k3_2: 10k3.2 10k4.1 150Nf.1 | length 128.1
  Top Layer w1: 10k4.1 35.087,49.737 35.673,50.323 35.673,50.776 43.009,58.112 58.513,58.112 58.84,58.439 58.84,59.689 10k3.2
  Layer 1 w1: 10k3.2@58.674,59.69 58.841,59.69 10k3.2
  Layer 2 w1: 10k3.2 58.888,59.805 60.081,60.998 60.081,61.031 66.939,67.89 75.024,67.89 78.141,71.007 78.141,78.078 83.045,82.982 96.97,82.982 101.399,78.553 101.399,73.164 105.828,68.735 107.278,68.735 108.973,70.43 108.973,72.599 110.669,74.294 122.333,74.294 122.713,73.914 150Nf.1
  Bottom Layer w1: 10k4.1 33.187,49.53 10k4.1@33.401,49.53
Net10k5_1: 10k5.1 15NF.1 NE5532P3.3 | length 165.7
  Top Layer w1: NE5532P3.3 46.414,68.862 64.947,68.862 68.032,71.947 68.032,76.897 71.117,79.982 76.435,79.982 78.141,78.276 78.141,70.766 81.545,67.362 87.666,67.362 90.69,70.386 90.69,79.578 92.594,81.482 100.592,81.482 102.183,79.891 102.183,69.139 94.406,61.362 79.06,61.362 79.046,61.376 70.283,61.376 69.683,60.776 69.683,59.168 63.206,52.691 10k5.1 ; 102.092,79.982 107.151,79.982 111.379,75.754 15NF.1
Net10k5_2: 10k5.2 10k6.1 39NF.2 | length 112.7
  Top Layer w1: 10k6.1 39.405,49.737 39.991,50.323 39.991,50.776 44.18,54.966 58.435,54.966 10k5.2
  Layer 2 w1: 10k5.2 63.254,59.689 65.274,59.689 67.205,57.758 122.365,57.758 128.026,52.097 137.254,52.097 39NF.2
  Bottom Layer w1: 39NF.2 140.783,55.626 39NF.2@140.97,55.626
Net10k7_2: 10k7.2 10k8.1 10NF.2 | length 129
  Top Layer w1: 10k8.1 42.809,50.93 42.809,51.398 44.273,52.862 54.109,52.862 56.195,50.776 56.195,49.766 57.849,48.112 59.927,48.112 61.581,49.766 61.581,53.341 66.331,58.091 66.331,58.476 67.524,59.669 10k7.2
  Layer 1 w1: 10k7.2 71.003,56.258 116.819,56.258 120.369,52.708 125.637,52.708 126.526,53.597 134.218,53.597 140.811,60.19 10NF.2
Net10k9_1: 10k9.1 470pF.2 NE5532P5.3 | length 149.2
  Top Layer w1: NE5532P5.3 66.532,75.462 66.532,77.518 70.496,81.482 77.057,81.482 79.641,78.898 79.641,71.387 82.166,68.862 87.045,68.862 89.19,71.007 89.19,80.199 91.972,82.982 112.026,82.982 120.714,74.294 ; 10k9.1 73.467,48.112 94.316,48.112 101.948,55.744 101.948,57.656 118.586,74.294 120.714,74.294 ; 470pF.2 121.593,72.701 121.593,73.416 120.714,74.294
Net10ka_1: 10ka.1 220ufa.1 lm386.5 | length 50.5
  Layer 1 w1: 220ufa.1 94.457,112.268 97.072,109.653 100.229,109.653 102.844,107.037 102.844,106.027 105.971,102.9 118.033,102.9 10ka.1 133.811,99.648 lm386.5
Net10ka_2: 10ka.2 10uf4.1 | length 53
  Bottom Layer w1: 10uf4.1 82.265,111.887 83.965,110.187 86.966,110.187 94.064,117.285 94.064,118.171 97.381,121.488 98.707,121.488 99.644,120.551 99.644,119.871 102.844,116.671 102.844,116.393 105.269,113.968 116.965,113.968 10ka.2
Net10ke_2: 10ke.2 ne55329.1 pot10k.3 speker2.1 | length 83.6
  Top Layer w1: 10ke.2 111.697,115.998 117.355,110.34 117.355,105.862 114.381,102.887 108.765,102.887 105.791,99.913 ne55329.1 107.541,99.413 114.136,99.413 117.428,96.121 117.428,92.439 120.721,89.147 124.429,89.147 128.867,84.709 speker2.1
  Bottom Layer w1: pot10k.3 109.299,116.253 109.299,116.046 10ke.2
Net10NF_1: 10NF.1 NE5532P4.6 NE5532P4.7 | length 94.7
  Top Layer w1: NE5532P4.6 60.697,73.248 60.697,75.383 59.043,77.037 59.043,78.957 66.068,85.982 125.473,85.982 10NF.1
Net10uf_1: 10uf.1 pot10k.2 | length 33.6
  Bottom Layer w1: 10uf.1 81.574,99.167 95.161,112.754 95.161,112.972 98.044,115.855 pot10k.2
Net10uf_2: 10uf.2 100k4.2 ne55328.5 | length 49.3
  Bottom Layer w1: 10uf.2 89.098,95.615 89.098,96.965 91.546,99.413 93.874,99.413 97.037,96.25 97.037,93.336 98.547,91.826 ne55328.5 ; 98.58,91.858 98.58,98.388 102.844,102.652 102.844,107.037 101.219,108.662 100k4.2
Net10ufau_1: 10ufau.1 lm386.1 | length 19.1
  Bottom Layer w1: lm386.1 130.302,107.061 10ufau.1
Net10ufau_2: 10ufau.2 lm386.8 | length 19.8
  Bottom Layer w1: 10ufau.2 137.513,93.27 137.513,107.47 lm386.8
Net12audio_2: 12audio.2 100,2.2 pot,5k.1 | length 28.1
  Bottom Layer w1: 12audio.2 155.782,87.63 159.967,91.815 159.967,91.959 163.075,95.067 164.434,95.067 167.543,98.175 171.959,98.175
Net12v2_1: 12v2.1 ne55328.4 ne55329.4 | length 32.5
  Bottom Layer w1: ne55328.4 94.46,88.293 104.041,88.293 ne55329.4 109.156,90.043 110.906,88.293 114.951,88.293 117.59,90.932 12v2.1
Net12v2_2: 12v2.2 ne55328.8 ne55329.8 | length 24.8
  Bottom Layer w1: ne55328.8 102.08,99.413 106.955,99.413 108.705,97.663 ne55329.8 117.602,93.472 12v2.2
Net12V_2: 12V.2 7812.3 o.1uf1.1 ZE1.1 | length 50.3
  Top Layer w1: 7812.3 62.357,116.586 o.1uf1.1
  Bottom Layer w1: 12V.2 33.677,118.386 40.364,118.386 7812.3 42.164,122.495 42.897,123.228 ZE1.1
Net12vled_2: 12vled.2 lm3914.5 | length 8.7
  Bottom Layer w1: 12vled.2 154.305,102.362 lm3914.5
Net15NF_2: 15NF.2 50kpot800Hz.2 | length 51
  Top Layer w1: 15NF.2 15NF.2@114.3,72.39
  Bottom Layer w1: 15NF.2 131.254,55.015 131.254,53.112 139.7,44.666 139.7,33.782 139.484,33.566 139.484,32.677 50kpot800Hz.2
Net15V_1: 15V.1 NE5532P2.8 NE5532P3.8 NE5532P4.8 NE5532P5.8 NE5532P6.8 NE5532P7.8 NE55321.8 | length 458.8
  Layer 1 w1: NE5532P5.8 73.592,79.982 74.107,79.982 81.006,79.982 82.756,78.232 NE5532P7.8 82.931,78.272 NE5532P7.8@82.931,78.613
  Layer 2 w1: NE5532P7.8 84.641,79.982 92.19,79.982 NE5532P6.8
  Bottom Layer w1: NE5532P2.8 40.572,79.982 47.994,79.982 NE5532P3.8 51.494,79.982 59.043,79.982 NE5532P4.8 ; 40.395,80.159 43.218,82.982 122.276,82.982 130.255,75.003 130.255,73.37 131.386,72.239 132.774,72.239 133.755,73.22 133.755,75.746 123.038,86.463 39.981,86.463 33.5,79.982 30.038,79.982 29.452,79.396 29.452,68.719 30.809,67.362 40.995,67.362 41.782,68.149 45.831,68.149 46.618,67.362 52.044,67.362 52.831,68.149 57.29,68.149 58.076,67.362 74.142,67.362 74.929,68.149 75.282,68.149 77.021,69.887 77.021,79.396 76.435,79.982 73.592,79.982 NE5532P5.8 ; NE5532P6.8 95.563,79.855 104.803,79.855 NE55321.8 120.644,78.105 125.405,73.344 125.405,72.203 128.369,69.239 134.016,69.239 136.755,71.978 136.755,73.202 139.347,75.794 164.399,75.794 172.298,67.895 172.298,47.584 15V.1
Net15V_2: 15V.2 NE5532P2.4 NE5532P3.4 NE5532P4.4 NE5532P5.4 NE5532P6.4 NE5532P7.4 NE55321.4 | length 231.8
  Layer 1 w1: NE5532P7.4 78.636,70.612 80.386,68.862 84.57,68.862 NE5532P6.4 88.07,68.862 97.31,68.862 NE55321.4
  Bottom Layer w1: NE5532P2.4 32.952,68.862 40.374,68.862 NE5532P3.4 45.489,70.612 47.239,68.862 51.423,68.862 NE5532P4.4 56.948,70.612 58.698,68.862 62.472,68.862 NE5532P5.4 65.972,68.862 73.521,68.862 NE5532P7.4 ; NE55321.4 102.183,67.235 115.01,67.235 136.426,45.819 136.426,33.396 138.783,31.039 140.109,31.039 141.2,32.13 141.2,45.287 137.254,49.233 137.254,56.729 150.708,70.183 167.889,70.183 170.798,67.274 170.798,48.624 15V.2
Net33NF_2: 33NF.2 50kpot250Hz.2 | length 94.3
  Top Layer w1: 50kpot250Hz.2 75.116,32.003 75.676,31.443 93.675,31.443 94.46,30.658 117.762,30.658 118.547,31.443 132.826,31.443 154.773,53.39 33NF.2
Net39NF_1: 39NF.1 NE5532P3.1 NE5532P3.2 | length 112.7
  Layer 1 w1: NE5532P3.2 44.729,75.692 49.019,79.982 65.386,79.982 68.252,77.117 68.252,71.727 75.171,64.809 127.799,64.809 134.718,57.89 134.718,57.061 39NF.1
  Bottom Layer w1: NE5532P3.2 NE5532P3.2@42.124,75.779 ; NE5532P3.1 NE5532P3.2@42.124,75.779 ; NE5532P3.2@42.291,75.946 NE5532P3.2@42.124,75.779
Net50kpot4kHz_1: 50kpot4kHz.1 50kpot16kHz.1 50kpot50Hz.1 50kpot250Hz.1 50kpot800Hz.1 NE5532P6.3 | length 264.9
  Top Layer w1: 50kpot250Hz.1 66.628,36.143 78.391,36.143 79.736,34.798 50kpot4kHz.1 90.603,37.898 106.885,37.898 50kpot50Hz.1 112.748,35.051 114.348,36.651 130.354,36.651 50kpot800Hz.1
  Bottom Layer w1: 50kpot16kHz.1 49.638,34.67 51.238,33.07 57.346,33.07 58.819,34.543 50kpot250Hz.1 69.25,34.543 69.81,35.103 73.932,35.103 76.092,32.943 80.012,32.943 83.212,36.143 86.158,36.143 ; NE5532P6.3 88.07,71.402 88.07,69.887 82.545,64.362 35.307,64.362 31.355,60.41 31.355,59.064 35.499,54.92 60.687,54.92 64.831,50.776 64.831,49.766 66.485,48.112 72.881,48.112 77.631,52.862 84.552,52.862 86.016,51.398 86.016,36.285 86.158,36.143 ; 50kpot4kHz.1 86.158,36.143
Net50kpot4kHz_3: 50kpot4kHz.3 50kpot16kHz.3 50kpot50Hz.3 50kpot250Hz.3 50kpot800Hz.3 100Ohm.2 NE5532P6.1 SPEKER.2 | length 404.3
  Bottom Layer w1: 50kpot16kHz.3 55.019,34.67 56.952,36.603 ; 100Ohm.2 89.103,53.525 89.103,33.784 88.517,33.198 86.489,33.198 86.244,33.443 82.633,33.443 80.633,31.443 ; NE5532P6.1 84.57,79.982 82.166,79.982 79.035,76.851 79.035,69.78 75.117,65.862 34.686,65.862 29.855,61.031 29.855,58.443 34.878,53.42 57.869,53.42 60.768,50.521 60.768,49.511 63.667,46.612 73.503,46.612 78.253,51.362 83.93,51.362 84.516,50.776 84.516,41.331 50kpot250Hz.3 75.668,36.603 56.952,36.603 ; SPEKER.2 164.719,65.913 164.084,65.278 161.028,65.278 152.623,56.873 152.623,55.762 144.526,47.665 144.526,31.214 141.351,28.039 137.541,28.039 133.426,32.154 133.426,36.193 132.84,36.779 124.16,36.779 118.292,30.911 116.689,30.911 110.949,36.651 108.718,36.651 106.865,34.798 50kpot4kHz.3 96.063,30.658 87.547,30.658 86.762,31.443 80.633,31.443 ; 56.952,36.603 41.614,36.603 40.695,35.684 40.695,33.656 43.821,30.53 68.912,30.53 71.985,33.603 73.311,33.603 75.471,31.443 80.633,31.443
Net50kpot16kHz_2: 50kpot16kHz.2 470pF.1 | length 156
  Top Layer w1: 50kpot16kHz.2 49.969,32.13 50.656,31.443 68.435,31.443 70.595,33.603 75.637,33.603 76.297,32.943 79.949,32.943 80.204,33.198 88.517,33.198 91.717,36.398 100.866,36.398 103.813,33.451 113.269,33.451 113.929,34.111 121.109,34.111 121.769,33.451 132.712,33.451 133.426,34.165 133.426,36.193 128.322,41.297 111.332,41.297 103.448,49.181 103.448,56.442 470pF.1
  Bottom Layer w1: 50kpot16kHz.2@49.911,32.131 49.912,32.13 50kpot16kHz.2
Net50kpot50Hz_2: 50kpot50Hz.2 100K.2 470NF.2 | length 72.7
  Layer 1 w1: 100K.2 80.729,59.601 82.572,57.758 119.855,57.758 470NF.2
  Bottom Layer w1: 50kpot50Hz.2 123.13,38.289 470NF.2
Net100K2_2: 100K2.2 SPEKER.1 | length 6.2
  Bottom Layer w1: 100K2.2 161.566,63.157 161.782,63.373 SPEKER.1
Net100k3_1: 100k3.1 speker2.2 | length 7.4
  Bottom Layer w1: speker2.2 142.621,89.535 100k3.1
Net100K_1: 100K.1 NE5532P7.6 NE5532P7.7 | length 186.8
  Layer 2 w1: 100K.1 80.663,45.232 81.05,45.232 92.076,56.258 116.819,56.258 122.48,50.597 138.264,50.597 142.304,54.637 142.304,56.107 141.588,56.823 141.588,57.651 142.691,58.754 146.732,58.754 155.447,67.469 155.447,69.597 154.861,70.183 151.195,70.183 142.766,61.754 89.274,61.754 81.141,69.887 81.141,71.402 NE5532P7.6
  Bottom Layer w1: NE5532P7.6 NE5532P7.7
Net100Ohm_1: 100Ohm.1 NE5532P6.2 | length 125.3
  Layer 1 w1: 100Ohm.1 77.597,49.737 75.972,51.362 70.803,51.362 69.683,50.242 69.683,49.232 68.563,48.112 66.485,48.112 64.831,49.766 64.831,51.412 57.114,59.129 57.114,59.491 51.916,64.689 42.27,64.689 37.072,69.887 37.072,78.957 39.597,81.482 85.984,81.482 88.07,79.396 88.07,77.068 87.484,76.482 87.245,76.482 86.455,75.692 NE5532P6.2
Net150Nf_2: 150Nf.2 NE5532P2.6 NE5532P2.7 | length 109.4
  Bottom Layer w1: NE5532P2.6 NE5532P2.7 37.072,77.442 37.072,78.957 43.078,84.963 122.417,84.963 132.013,75.366 132.013,73.981 150Nf.2
Net220ufa_2: 220ufa.2 sp.2 | length 20.1
  Top Layer w1: 220ufa.2 99.528,109.601 sp.2
  Bottom Layer w1: sp.2 sp.2@115.824,109.601
Net680NF_2: 680NF.2 NE55321.1 NE55321.2 | length 68.8
  Bottom Layer w1: NE55321.2 NE55321.1 101.183,78.105 103.506,75.782 103.506,71.058 105.828,68.735 107.278,68.735 109.246,70.704 109.246,72.872 110.669,74.294 122.333,74.294 123.905,72.722 123.905,71.582 127.748,67.739 138.169,67.739 142.411,71.981 142.411,72.1 144.605,74.294 146.733,74.294 147.612,73.416 147.612,72.701 680NF.2
Net2200UF2_1: 2200UF2.1 7912.1 D3.2 D4.2 | length 31.8
  Bottom Layer w1: 28.448,103.487 D3.2 D4.2@33.366,103.487 ; D4.2 33.147,109.728 7912.1@34.999,111.58 ; 7912.1 37.225,111.506 38.752,109.979 38.752,109.683 40.278,108.156 44.05,108.156 45.514,109.62 45.514,110.654 46.747,111.887 2200UF2.1
Net2200UF_2: 2200UF.2 7812.1 D1.1 D2.1 | length 41.6
  Top Layer w1: 40.767,90.975 40.767,101.068 39.221,102.614 39.221,108.563 7812.1
  Bottom Layer w1: D2.1@37.592,92.093 37.655,92.157 40.957,92.157 D1.1 ; 39.963,92.22 D1.1 ; 2200UF.2 52.85,92.22 D1.1
Net7912_2: 7912.2 trans.2 | length 34.9
  Bottom Layer w1: trans.2 26.419,85.468 26.419,92.185 26.902,92.668 26.902,104.233 30.502,107.833 30.502,110.097 34.336,113.931 34.81,113.931 7912.2
NetD1_2: D1.2 D3.1 trans.3 | length 22.4
  Layer 2 w1: D3.1 29.764,92.647 30.308,92.647 D1.2
  Bottom Layer w1: trans.3 28.194,91.839 D3.1@28.702,92.347
NetD2_2: D2.2 D4.1 trans.1 | length 27.1
  Layer 2 w1: D2.2 37.465,103.378 D2.2@37.592,103.251
  Bottom Layer w1: trans.1 31.23,84.189 31.23,90.304 32.736,91.811 32.847,91.811 33.092,92.056 33.092,92.166 D4.1@33.202,92.166 ; D4.1 33.691,92.111 36.703,95.123 36.703,102.708 37.349,103.353 D2.2@37.349,103.516
NetINPUT_2: INPUT.2 NE5532P7.5 | length 114.4
  Top Layer w1: NE5532P7.5 81.141,72.362 81.141,78.957 86.666,84.482 123.881,84.482 137.319,71.044 141.474,71.044 143.039,72.61 143.039,72.728 144.605,74.294 150.75,74.294 156.648,68.396 156.648,65.415 162.547,59.517 164.003,59.517 INPUT.2
Netinputled_2: inputled.2 LED1.2 LED2.2 LED3.2 LED4.2 LED6.2 LED7.2 lm3914.3 lm3914.9 | length 115.6
  Top Layer w1: lm3914.3 152.881,112.05 162.517,112.05 166.115,115.649 166.115,117.015 163.953,119.178 152.851,119.178 150.495,121.533 LED7.2
  Bottom Layer w1: LED1.2 113.538,121.799 115.332,123.593 118.088,123.593 LED2.2 119.888,121.799 121.682,123.593 124.311,123.593 LED3.2 126.111,121.787 126.851,121.047 ; LED4.2 130.661,119.993 127.905,119.993 126.851,121.047 ; lm3914.3 150.875,110.044 162.815,110.044 lm3914.9 164.465,102.743 inputled.2 ; LED7.2 148.568,123.466 146.193,123.466 144.399,121.672 LED6.2 141.099,124.966 129.278,124.966 126.851,122.539 126.851,121.047
NetLED1_1: LED1.1 lm3914.1 | length 33.6
  Bottom Layer w1: LED1.1 122.76,115.111 137.428,115.111 lm3914.1
NetLED2_1: LED2.1 lm3914.18 | length 24.3
  Top Layer w1: LED2.1 127.889,116.332 lm3914.18
  Bottom Layer w1: LED2.1@122.174,121.92 122.301,121.793 LED2.1
NetLED3_1: LED3.1 lm3914.17 | length 22.6
  Bottom Layer w1: LED3.1 130.324,123.466 135.62,123.466 136.716,122.37 136.716,120.835 139.184,118.366 144.651,118.366 lm3914.17
NetLED4_1: LED4.1 lm3914.16 | length 18.6
  Bottom Layer w1: LED4.1 134.989,121.551 134.989,120.44 140.747,114.682 147.575,114.682 lm3914.16
NetLED5_1: LED5.1 lm3914.15 | length 12.8
  Bottom Layer w1: LED5.1 142.77,119.866 145.582,119.866 147.209,118.239 149.858,118.239 lm3914.15
NetLED5_2: LED5.2 LED8.2 LED9.2 LED10.2 | length 53.8
  Top Layer w1: LED5.2 138.557,121.545 140.478,123.466 154.537,123.466 LED8.2
  Layer 1 w1: LED5.2 138.557,121.545 140.478,123.466 154.537,123.466 LED8.2
  Bottom Layer w1: LED8.2 156.337,121.672 158.131,123.466 160.76,123.466 LED9.2 162.433,121.799 164.227,123.593 166.602,123.593 LED10.2
NetLED6_1: LED6.1 lm3914.14 | length 9.6
  Bottom Layer w1: LED6.1 148.866,119.739 150.898,119.739 lm3914.14
NetLED7_1: LED7.1 lm3914.13 | length 6.8
  Bottom Layer w1: LED7.1 156.788,117.786 156.788,116.389 lm3914.13
NetLED8_1: LED8.1 lm3914.12 | length 5.5
  Bottom Layer w1: LED8.1 158.877,116.921 159.385,116.413 lm3914.12
NetLED9_1: LED9.1 lm3914.11 | length 6.7
  Bottom Layer w1: lm3914.11 164.973,119.38 LED9.1
NetLED10_1: LED10.1 lm3914.10 | length 8.8
  Bottom Layer w1: lm3914.10 164.522,116.389 165.798,116.389 171.069,121.66 LED10.1
Netlm386_3: lm386.3 pot,5k.2 | length 51.8
  Top Layer w1: lm386.3 134.973,110.97 138.855,110.97 144.581,105.245 168.527,105.245 169.078,105.795 174.499,105.795
Netpot10k_1: pot10k.1 VOLUME.1 | length 12.8
  Bottom Layer w1: VOLUME.1 80.652,123.578 84.921,123.578 86.071,122.428 pot10k.1
pads on no net: 12audio.1 12vled.1 inputled.1 lm386.6 lm386.7 NE5532P2.1 NE5532P2.2 NE5532P2.3 NE5532P3.5 NE5532P3.6 NE5532P3.7 NE5532P4.1 NE5532P4.2 NE5532P4.3 NE5532P5.5 NE5532P5.6 NE5532P5.7 NE5532P6.5 NE5532P6.6 NE5532P6.7 NE5532P7.1 NE5532P7.2 NE5532P7.3 NE55321.5 NE55321.6 NE55321.7 ne55328.1 ne55328.2 ne55328.3 ne55329.5 ne55329.6 ne55329.7
copper on no net:
  other v1: 27.559,27.432 175.768,27.559 27.432,124.968 175.895,124.968

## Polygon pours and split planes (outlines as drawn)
GND on Top Layer "NONET_L-01_P-001" (solid, remove dead copper, pour order 1): 35.814,124.841 35.941,124.841 36.195,125.095 170.815,125.095 175.514,120.396 175.768,120.396 175.514,120.142 175.514,33.02 169.799,27.305 169.799,27.051 35.433,27.051 26.416,36.068 26.416,116.459
GND on Layer 1 "NONET_L-01_P-001" (solid, remove dead copper, pour order 2): 37.465,122.174 38.227,121.412 168.275,121.412 173.101,116.586 173.101,116.459 175.006,114.554 175.006,33.274 169.926,28.194 36.195,28.194 28.067,36.322 28.067,36.957 27.94,37.084 27.94,114.681
GND on Layer 2 "NONET_L-01_P-001" (solid, remove dead copper, pour order 3): 40.513,118.618 40.894,118.999 163.449,118.999 169.799,112.649 169.799,108.839 169.799,44.323 167.767,42.291 153.924,42.291 141.224,29.591 137.922,29.591 137.795,29.718 36.957,29.718 31.496,38.989 30.226,108.331
GND on Bottom Layer "NONET_L-01_P-001" (solid, remove dead copper, pour order 0): 34.29,126.238 171.831,126.238 176.657,121.412 176.657,31.369 171.45,26.162 170.942,26.67 32.004,26.67 26.162,32.512 26.162,117.729 34.29,125.857

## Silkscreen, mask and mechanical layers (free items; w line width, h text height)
Top Overlay:
  lines w0.254: 26.543,75.565 26.543,34.544 34.544,26.543 170.434,26.543 175.514,31.623 176.022,31.623 175.514,32.131 175.514,69.215 174.117,70.612 173.736,70.612 169.418,74.93 164.338,74.93 160.528,78.74 147.193,78.74 143.256,82.677 36.449,82.677 29.337,75.565 28.575,75.565 28.448,75.438 26.67,75.438 ; 26.416,77.089 26.416,117.221 26.797,117.602 26.924,117.602 26.924,117.729 34.925,125.73 73.025,125.73 74.041,124.714 75.565,123.19 75.565,88.138 36.068,88.138 36.068,84.328 28.575,76.835 26.67,76.835 26.416,77.089 ; 76.327,86.741 77.597,85.471 114.808,85.471 116.459,87.122 116.459,98.171 116.078,98.552 116.078,99.441 110.49,105.029 110.49,115.57 110.871,115.951 106.807,120.015 106.807,125.476 106.045,126.238 76.327,126.238 76.327,86.741 ; 108.966,120.269 108.966,126.111 171.45,126.111 176.403,121.158 176.403,72.009 176.022,71.628 174.879,71.628 169.418,77.089 165.1,77.089 161.036,81.153 146.05,81.153 143.129,84.074 121.539,84.074 117.221,88.392 117.221,99.568 111.76,105.029 111.76,117.475 108.966,120.269 ; 154.559,39.878 154.686,39.751 154.686,27.305 154.813,27.432 169.291,27.432 173.228,31.369 173.228,32.385 173.355,32.512 173.355,40.132 173.101,39.878 154.559,39.878
  text "POWER" at 34.544,122.682 h1.52
  text "LED" at 150.876,92.71 h1.52
  text "5 BAND" at 29.464,42.164 h1.52
  text "ISURU ENTC 5BAND AUDIO EQULIZER" at 156.591,30.734 h1.52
